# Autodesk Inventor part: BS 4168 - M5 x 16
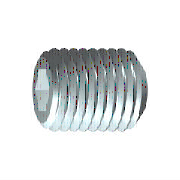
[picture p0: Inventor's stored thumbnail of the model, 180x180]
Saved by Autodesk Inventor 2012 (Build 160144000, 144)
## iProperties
IsCustomPart: 0
Created: 2008-01
Part Number: BS 4168 - M5 x 16
Material: Steel, Mild
Description: Hexagon socket screws and wrench keys, metric series- Specification for hexagon set screws with flat point
Document SubType Name: Modeling
Standard: BS 4168
Designer: latalom
Standards Organization: BSI
Language: en-US
Size Designation: M5 x 16
Categories: <MemberInstance><Categories><Category DisplayName="Fasteners" InternalName="e4da775c-781d-43d5-af7c-5136215cf5a6" Mnemonic="FSTN"><Category DisplayName="Bolts"
Density: 7.86 g/cm^3
Mass: 2.29997 g
Surface Area: 3.08393 cm^2
Volume: 0.292617 cm^3
Author: latalom
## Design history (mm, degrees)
revolve "Body" stored, may be unused: angle "d6" = 90 deg
sketch "Sketch2"
  geometry: L1 (-0.722, 1.25)-(0.722, 1.25); L2 (0.722, 1.25)-(1.443, 0); L3 (1.443, 0)-(0.722, -1.25); L4 (0.722, -1.25)-(-0.722, -1.25); L5 (-0.722, -1.25)-(-1.443, 0); L6 (-1.443, 0)-(-0.722, 1.25); A1 r 1.443 centre (0, 0) between (-0.722, 1.25) and (0.722, 1.25) reference; 2 further points
  constraints: 12 end point, 2 point on circle, 1 coincident, 1 horizontal, 11 other
extrude "Slot" join sketch "Sketch2" taper "d9" = 0 deg; stored distance "d21" = 10
workaxis "Work Axis1"
workplane "Work Plane1"
body "Solid1"
chamfer "Chamfer1" distance "d7" = 0.49076 (= -0.5 x GD1 + 0.5 x NND); stored, may be unused: angle "d8" = 45 deg (= FAWI), second distance "d29" = 0.49076 (= -0.5 x GD1 + 0.5 x NND)
feature "Thread" dims "d11" = 16 (= NLG), "d12" = 0
chamfer "Chamfer2" distance "d13" = 0.49076 (= -0.5 x GD1 + 0.5 x NND); stored, may be unused: angle "d14" = 45 deg (= FAWI), second distance "d30" = 0.49076 (= -0.5 x GD1 + 0.5 x NND)
sketch "Sketch1"
  geometry: L1 (0, 0)-(12.167, 0); L2 (16, 1.443)-(16, 2.5); L3 (16, 2.5)-(0, 2.5); L4 (16, 1.443)-(13, 1.443); L5 (13, 1.443)-(12.167, 0); L6 (0, -0.5)-(0, 3) reference; L7 (0, 2.5)-(0, 0)
  constraints: 13 end point, 3 parallel, 1 collinear, 1 perpendicular, 1 point on line
  dimensions: "d0" = 3 distance of L2.start L4.end (= INTI); "d1" = 60 deg angle of L5 L1; "d2" = 5 diameter of L3 L1 (= NND); "d3" = 2.88675 diameter of L4 L1 (= 1.1547 x SW); "d5" = 16 distance from line of L2 L3.end (= NLG)
other parameters: "NND" = 5 [user parameter; used in 5 equation terms], "NLG" = 16 [user parameter; used in 2 equation terms], "INTI" = 3 [user parameter; used in 1 equation term], "FAWI" = 45 deg [user parameter; used in 2 equation terms], "SW" = 2.5 [user parameter; used in 2 equation terms], "GD1" = 4.01848 (= THREADDIA - 1.2269 x PTC) [user parameter; used in 4 equation terms], "d4" = 0, "FAWI1" = 45 deg [user parameter], "d15" = 0, "d31" = 0, "GUL" = 0.49076 (= 0.61345 x PTC) [user parameter], "SPD" = 3.5 [user parameter], "TPU" = 12.5 (computed from PTC) [user parameter], "TOA" = 30 deg [user parameter], "THREADDIA" = 5 [user parameter; used in 1 equation term], "PTC" = 0.8 [user parameter; used in 4 equation terms], "GAL" = 0.49076 (= 0.61345 x PTC) [user parameter], "E0" = 2.8875 (= 1.155 x SW) [user parameter]
